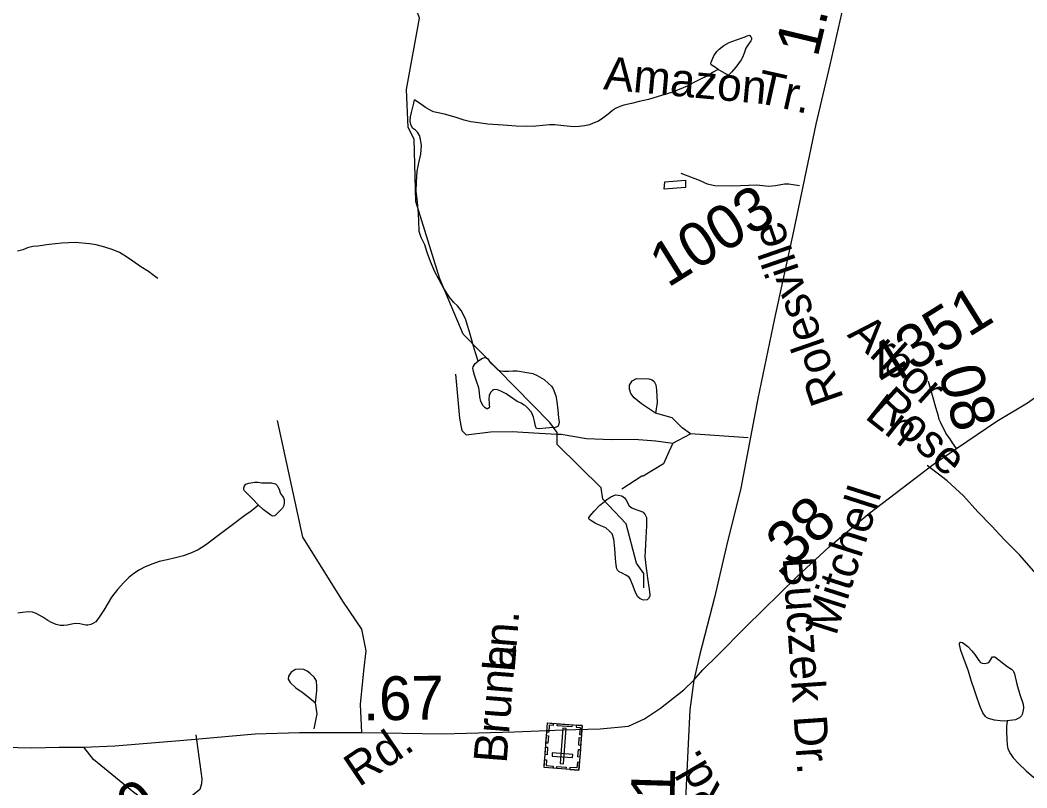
# Model space of a CAD drawing. Extents: x 2001466 to 31450019, y -30647475 to 847247.
# Drawn here: x 2159166 to 2164923, y 774589 to 778978 of the extents above; entities that cross this region are included whole.
import ezdxf

# ---------------------------------------------------------------- set-up
doc = ezdxf.new("R2010")
doc.units = 0
for name, color, linetype in [('Exist Cultural Cemetery CELL', 7, 'Continuous'), ('Exist Hydrographic Creek Single Shore', 7, 'Continuous'), ('Exist Hydrographic Misc Water Feature', 7, 'Continuous'), ('Exist Road Non-System Type 51', 7, 'Continuous'), ('Exist Road Non-System Type 51 Label', 7, 'Continuous'), ('Exist Road Secondary Mileage Hundredths English Label', 7, 'Continuous'), ('Exist Road Secondary Type 51 Attributed', 7, 'Continuous'), ('Exist Road Secondary Type 51 Label', 7, 'Continuous'), ('Exist Road Secondary Type 51 Number Label', 7, 'Continuous')]:
    doc.layers.add(name, color=color, linetype=linetype)

msp = doc.modelspace()

# ---------------------------------------------------------------- linework, layer by layer
at = {"layer": 'Exist Cultural Cemetery CELL'}
for points in [[(2162360.6, 774691), (2162162.1, 774706.1), (2162181.4, 774960), (2162379.9, 774944.9)], [(2162214.4, 774957.5), (2162213.6, 774946), (2162191.6, 774947.7), (2162188.6, 774907.4), (2162177.5, 774908.2), (2162181.4, 774960)], [(2162321.7, 774937.8), (2162237.1, 774944.3), (2162238, 774955.6), (2162322.6, 774949.2)], [(2162346.9, 774947.4), (2162346.1, 774935.9), (2162368, 774934.3), (2162364.9, 774894), (2162376, 774893.1), (2162380, 774944.9)], [(2162187.3, 774887.1), (2162184, 774843.9), (2162172.6, 774844.7), (2162175.9, 774887.9)], [(2162254.2, 774728.5), (2162272.8, 774727.1), (2162288.1, 774929.3), (2162269.5, 774930.7)], [(2162374.7, 774875.2), (2162371.4, 774832), (2162360, 774832.9), (2162363.3, 774876.1)], [(2162182.2, 774821.3), (2162179, 774778.2), (2162167.6, 774779), (2162170.9, 774822.2)], [(2162325.1, 774762), (2162326.5, 774780.6), (2162209.1, 774789.5), (2162207.7, 774770.9)], [(2162369.6, 774808.2), (2162366.3, 774765), (2162354.9, 774765.8), (2162358.2, 774809)], [(2162165.3, 774749.3), (2162176.7, 774748.5), (2162174.2, 774716.4), (2162214.7, 774713.3), (2162213.8, 774702.2), (2162162.1, 774706.1)], [(2162286.8, 774696.7), (2162235.1, 774700.6), (2162236, 774711.9), (2162287.7, 774708)], [(2162363.9, 774734.2), (2162352.6, 774735.1), (2162350.2, 774703), (2162309.7, 774706.1), (2162308.9, 774695), (2162360.6, 774691)]]:
    msp.add_lwpolyline(points, close=True, dxfattribs=at)
at = {"layer": 'Exist Hydrographic Creek Single Shore'}
for points in [[(2162195.3, 776678.1), (2161700.3, 777183.6), (2161565.1, 777498.1), (2161429.2, 777940.4), (2161419.2, 778298.2), (2161385.3, 778364.5), (2161376.3, 778581.3), (2161449.3, 778989.8), (2161347.2, 779280.6), (2161263.3, 779397.2), (2160987.3, 779563.5), (2160886.2, 779710), (2160878.2, 779779), (2160818.1, 779911.5), (2160516.3, 780291.7), (2160201, 780633.1)], [(2162237.3, 776611.6), (2162237.3, 776621.5), (2162195.3, 776678.1)], [(2162733.1, 775732.1), (2162733.1, 775814.1), (2162691.3, 775874), (2162631.2, 776098.3), (2162497.3, 776238.9), (2162488.3, 776304.7), (2162237.3, 776552.5), (2162237.3, 776611.6)]]:
    msp.add_lwpolyline(points, dxfattribs=at)
at = {"layer": 'Exist Hydrographic Misc Water Feature'}
for points in [[(2163157.8, 778696.5), (2163147.7, 778702.5), (2163117.8, 778722), (2163115.8, 778727.9), (2163117.4, 778737.8), (2163133.2, 778774), (2163149.2, 778798.4), (2163163.3, 778812.4), (2163191, 778832.6), (2163220.7, 778850.8), (2163262.6, 778864.8), (2163306.7, 778881.3), (2163332.5, 778891.1), (2163338.6, 778889.4), (2163342.5, 778885.2), (2163346.6, 778881.3), (2163348.5, 778875.3), (2163348.5, 778867.2), (2163344.6, 778859.3), (2163330.9, 778841.1), (2163316.7, 778817.2), (2163309.3, 778795.2), (2163301.3, 778772.9), (2163297.4, 778765), (2163289.6, 778751.2), (2163259.7, 778709), (2163234.1, 778680.9), (2163215.8, 778660.5), (2163208, 778666.6), (2163157.8, 778696.5)], [(2163157.8, 778696.5), (2163149.8, 778692.4), (2163126.2, 778678.1), (2163101.8, 778661.9), (2163064.3, 778643.7), (2163014.5, 778619.6), (2162980.4, 778601.2), (2162934.5, 778580.9), (2162891, 778564.8), (2162832.8, 778546.4), (2162790.7, 778534.1), (2162758.8, 778523.9), (2162706.7, 778512), (2162662.8, 778501.5), (2162619.1, 778491.5), (2162595.3, 778483.4), (2162571.1, 778473.2), (2162553.3, 778460.9), (2162529.5, 778441), (2162497.5, 778416.6), (2162473.5, 778400.4), (2162443.8, 778388.2), (2162421.7, 778380.2), (2162394, 778373.9), (2162362.2, 778369.7), (2162332, 778367.8), (2162276.1, 778373.4), (2162224, 778379.3), (2162194, 778378.9), (2162154.3, 778376.4), (2162114.1, 778372.4), (2162063.8, 778370.2), (2162001.7, 778371.9), (2161927.9, 778377.4), (2161839.9, 778383), (2161788, 778390.4), (2161744, 778396.3), (2161706, 778406.1), (2161653.7, 778423.7), (2161591.8, 778439.6), (2161529.5, 778453.1), (2161513.9, 778461.1), (2161483.5, 778478.6), (2161457.3, 778496.8), (2161421.2, 778522.6)], [(2161785.8, 777028.9), (2161769.6, 777076.8), (2161759.3, 777114.9), (2161744.8, 777160.9), (2161734.7, 777202.6), (2161724.5, 777232.5), (2161714.4, 777264.4), (2161700.3, 777296.2), (2161688.2, 777318.3), (2161666.2, 777344.3), (2161645.7, 777364.1), (2161621.7, 777394.1), (2161589.5, 777443.6), (2161563.1, 777493.4), (2161536.6, 777539.2), (2161512.5, 777597.2), (2161494.2, 777649.1), (2161479.8, 777693), (2161459.8, 777735), (2161447.4, 777768.9), (2161445, 777830.9), (2161444.8, 777870.7), (2161440.7, 777916.8), (2161436.6, 777956.7), (2161430, 777998.7), (2161431.9, 778050.8), (2161435.8, 778114.7), (2161445, 778162.8), (2161457.3, 778210.8), (2161461, 778260.6), (2161456.3, 778296.6), (2161450.5, 778318.6), (2161438.2, 778336.6), (2161426.3, 778348.6), (2161410.3, 778360.3), (2161400.1, 778380.5), (2161395.8, 778400.3), (2161398, 778424.3), (2161403.8, 778450.6), (2161417.5, 778502.4), (2161421.2, 778522.6)], [(2162971.8, 778021.5), (2162849.8, 778010.8), (2162853.3, 778052.9), (2162971.6, 778063.4), (2162971.8, 778021.5)], [(2159953.6, 777500.3), (2159939.5, 777510.2), (2159925.3, 777522.4), (2159899.5, 777540.2), (2159855.2, 777568), (2159810.7, 777599.4), (2159775, 777625.5), (2159734.4, 777649.1), (2159692.8, 777666.7), (2159651, 777680.8), (2159600.5, 777692.5), (2159562.4, 777698.2), (2159480.4, 777705.8), (2159404.3, 777703.1), (2159332.7, 777694.8), (2159266.9, 777686.5), (2159238.8, 777684.3), (2159208.7, 777676.3), (2159180.6, 777663.9), (2159151.1, 777657.8)], [(2162193.6, 776647.6), (2162171.5, 776645.2), (2162131.7, 776641.1), (2162119.6, 776642.9), (2162117.8, 776646.9), (2162113.5, 776656.9), (2162107.5, 776685), (2162101.8, 776708.9), (2162089.5, 776736.8), (2162066.9, 776762.5), (2162055, 776772.4), (2162045, 776778.4), (2162030.8, 776788.6), (2162013, 776796.2), (2162002.9, 776802.1), (2161970.9, 776824), (2161944.5, 776841.8), (2161914.6, 776857.8), (2161896.3, 776863.7), (2161880.5, 776865.7), (2161872.3, 776865.3), (2161866.6, 776861.3), (2161856.5, 776849.5), (2161848.9, 776831.2), (2161846.9, 776809.5), (2161849.1, 776789.3), (2161848.7, 776777.2), (2161849.4, 776767.4), (2161847.5, 776761.2), (2161839.3, 776755.5), (2161835.4, 776755.3), (2161825.4, 776761.3), (2161813.3, 776773.2), (2161801.2, 776797), (2161794.8, 776825.2), (2161792.8, 776848.9), (2161788.5, 776876.8), (2161776.1, 776914.8), (2161764.5, 776949), (2161757.9, 776968.6), (2161754, 776988.7), (2161756.3, 776996.9), (2161767.7, 777015), (2161785.8, 777028.9)], [(2161785.8, 777028.9), (2161789.9, 777032.8), (2161809.8, 777045.2), (2161823.5, 777049.2), (2161833.4, 777047.3), (2161839.7, 777041.1), (2161853.9, 777021.5), (2161877.9, 776997.6), (2161897.7, 776979.5), (2161911.7, 776973.8), (2161930.1, 776971.8), (2161960.3, 776971.7), (2161984.1, 776972.2), (2162007.9, 776972.2), (2162020, 776970.4), (2162064, 776964.5), (2162097.9, 776958.6), (2162122.3, 776946.8), (2162162.1, 776923.3), (2162188.3, 776901.5), (2162204.7, 776885.2), (2162214.3, 776869.6), (2162228.5, 776829.7), (2162234.6, 776797.5), (2162241.2, 776747.5), (2162245.5, 776703.8), (2162247.8, 776679.6), (2162247.4, 776669.9), (2162243.5, 776659.5), (2162240, 776655.6), (2162225.8, 776649.6), (2162193.6, 776647.6)], [(2160529, 776206.1), (2160496.4, 776239.8), (2160448.2, 776287.6), (2160444.3, 776295.5), (2160444.5, 776303.6), (2160448.2, 776315.6), (2160456.2, 776325.8), (2160474.3, 776331.5), (2160508.1, 776335.7), (2160528, 776336), (2160546, 776332.1), (2160604.1, 776332.6), (2160616, 776328.4), (2160626, 776326.5), (2160636.3, 776316.8), (2160639.7, 776310.6), (2160646.5, 776296.6), (2160652.1, 776276.6), (2160656.4, 776268.7), (2160666.6, 776257), (2160672.6, 776246.8), (2160676.5, 776234.8), (2160676.5, 776217), (2160674.6, 776203.1), (2160666.8, 776188.8), (2160658.6, 776180.7), (2160643.2, 776164.8), (2160622.9, 776144.8), (2160611, 776142.5), (2160598.7, 776148.4), (2160554.9, 776180.2), (2160529, 776206.1)], [(2162513.9, 776231.2), (2162521.7, 776237.3), (2162543.5, 776253.5), (2162569.9, 776263.7), (2162585.7, 776261.7), (2162606, 776257.8), (2162621.6, 776247.8), (2162633.9, 776232.1), (2162641.9, 776213.8), (2162649.7, 776202.2), (2162664.2, 776190.2), (2162676.5, 776184.3), (2162698.3, 776176.6), (2162716.3, 776170.6), (2162728, 776164.7), (2162740.7, 776150.6), (2162748.5, 776134.8), (2162748.7, 776086.6), (2162745, 776018.6), (2162739.5, 775944.8), (2162737.6, 775910.6), (2162741.7, 775876.7), (2162746.2, 775844.8), (2162749.9, 775819), (2162752.4, 775802.8), (2162754.2, 775788.8), (2162762.9, 775725), (2162766.8, 775692.8), (2162766.8, 775685.1), (2162759, 775670.8), (2162751, 775664.7), (2162731.3, 775662.8), (2162711, 775668.8), (2162698.9, 775680.7), (2162684.9, 775706.3), (2162671, 775742.5), (2162654.6, 775784.4), (2162648.4, 775794.2), (2162630.2, 775805.9), (2162608.5, 775816.1), (2162592.3, 775823.8), (2162582, 775833.9), (2162578.3, 775841.7), (2162574, 775861.9), (2162569.7, 775899.9), (2162567.4, 775957.8), (2162561.3, 776009.9), (2162551.2, 776041.4), (2162536.9, 776057.3), (2162514.7, 776075.3), (2162486.4, 776087.3), (2162454.7, 776103), (2162434.8, 776113), (2162424.5, 776121), (2162418.8, 776126.7), (2162418.6, 776132.8), (2162424.5, 776142.9), (2162448.3, 776170.9), (2162481.9, 776205.2), (2162505.9, 776223.5), (2162513.9, 776231.2)], [(2160529, 776206.1), (2160487.2, 776171.8), (2160450.9, 776145.6), (2160373.2, 776087.2), (2160303.7, 776034.8), (2160256.1, 775998.6), (2160226, 775976.4), (2160184.1, 775950.3), (2160146.4, 775932.1), (2160100.3, 775915.9), (2160054.5, 775903.3), (2160006.8, 775893.1), (2159961, 775883), (2159924.9, 775870.6), (2159881.1, 775852.5), (2159849.1, 775836.2), (2159815.2, 775814.2), (2159787.3, 775792.1), (2159759.7, 775763.8), (2159721.9, 775723.6), (2159687.7, 775679.3), (2159668.4, 775647.3), (2159644.4, 775605.1), (2159618.6, 775565.2), (2159598.5, 775539.1), (2159585, 775531), (2159569.2, 775522.8), (2159553.2, 775518.8), (2159541.1, 775518.5), (2159507.2, 775526.5), (2159481.2, 775528.4), (2159460.9, 775524.2), (2159435.1, 775519.9), (2159414.8, 775517.7), (2159395.3, 775517.8), (2159371.1, 775523.5), (2159345.3, 775533.6), (2159324.5, 775545.2), (2159294.8, 775565.1), (2159256.9, 775585.1), (2159236.6, 775593), (2159212.6, 775594.6), (2159178.5, 775592.4), (2159152.9, 775588.6)], [(2164810.5, 774972.8), (2164794.3, 774970.7), (2164770.5, 774972.7), (2164738.3, 774976.4), (2164704.7, 774986.3), (2164692, 774991.9), (2164686.2, 774998), (2164672.1, 775018), (2164657.9, 775047.8), (2164639.7, 775101.6), (2164621.2, 775153.5), (2164607.3, 775197.4), (2164588.8, 775255.3), (2164558.7, 775339), (2164546.4, 775375), (2164538, 775409.1), (2164538.2, 775415.2), (2164540, 775421), (2164545.8, 775422.9), (2164556, 775421), (2164586.2, 775397.3), (2164608.1, 775373.3), (2164626.2, 775351.5), (2164648.5, 775317.7), (2164658.4, 775305.7), (2164668.4, 775301.7), (2164682.6, 775300), (2164700.2, 775304.2), (2164710.4, 775312), (2164716.4, 775322.1), (2164722.3, 775332.1), (2164726.2, 775338), (2164732.4, 775338.3), (2164740.4, 775338.3), (2164748.4, 775332.3), (2164808.9, 775284.5), (2164834.7, 775266.9), (2164845, 775258.8), (2164846.8, 775254.9), (2164853, 775241), (2164865.1, 775181.2), (2164883.5, 775123.2), (2164901.8, 775067.2), (2164904, 775047.5), (2164902, 775033.2), (2164896.4, 775009.3), (2164892.1, 775001), (2164880.2, 774989), (2164858.1, 774978.9), (2164810.5, 774972.8)], [(2164810.5, 774972.8), (2164806.4, 774940.5), (2164806.8, 774912.9), (2164809.1, 774864.7), (2164811.1, 774834.7), (2164815.2, 774813), (2164829.4, 774782.9), (2164845.4, 774761), (2164878, 774727.3), (2164919.8, 774685.6), (2164960.2, 774649.5), (2164994.2, 774622.1), (2165020.7, 774601.8), (2165044.5, 774582)]]:
    msp.add_lwpolyline(points, dxfattribs=at)
at = {"layer": 'Exist Road Non-System Type 51'}
for p in [(2162898.5, 776558.7), (2163329, 776590.6)]:
    msp.add_line(p, (2162999.8, 776613.3), dxfattribs=at)
for points in [[(2162944.1, 778103.3), (2163049.1, 778062.8), (2163094.6, 778041.7), (2163138.4, 778032.6), (2163238.3, 778030.2), (2163378.4, 778036.8), (2163448.2, 778029.1), (2163486.3, 778032.1), (2163536.5, 778042.9), (2163562.5, 778042.3), (2163622.2, 778032.8)], [(2161656.4, 776954.9), (2161678.3, 776702.4), (2161685.2, 776660.3), (2161692.6, 776632.1), (2161715.9, 776607.5), (2161856.3, 776624.1), (2161980.4, 776627.1), (2162134.1, 776617.3), (2162237.3, 776611.6)], [(2162798.7, 776731.1), (2162720, 776785), (2162676.9, 776818.1), (2162657.5, 776842.6), (2162650.1, 776868.7), (2162650.6, 776890.7), (2162665.3, 776916.4), (2162691.6, 776929.7), (2162761.5, 776928), (2162779.4, 776921.6), (2162791.1, 776911.3), (2162800.7, 776893.1), (2162805.9, 776862.9), (2162808.2, 776792.9), (2162798.7, 776731.1)], [(2162999.8, 776613.3), (2162951.5, 776647.4), (2162894.7, 776704.2), (2162798.7, 776731.1)], [(2161120.7, 774906.1), (2161112.1, 775065.5), (2161130.6, 775258.6), (2161144.8, 775372.2), (2161119.2, 775495.8), (2161015.6, 775650.6), (2160782.9, 776022.6), (2160638.1, 776690)], [(2162237.3, 776611.6), (2162259.9, 776610.3), (2162405.3, 776586.8), (2162547.1, 776581.3), (2162677.1, 776582.1), (2162800.9, 776573.1), (2162898.5, 776558.7)], [(2162898.5, 776558.7), (2162875.3, 776509.3), (2162845.7, 776442.1), (2162728, 776370.9), (2162722, 776371.1), (2162606.2, 776295.9)], [(2166520.7, 774794.9), (2166259.7, 774833.3), (2165987.6, 774909.9), (2165934.1, 774927.2), (2165884.6, 774950.4), (2165793.6, 774988.6), (2165671.3, 775057.5), (2165557.5, 775146.3), (2165447.7, 775234.9), (2165334.2, 775339.7), (2165246.5, 775429.8), (2165165.6, 775582.4), (2165086.1, 775661.9), (2165003.8, 775781.2), (2164881.7, 775920.4), (2164793.8, 776008.4), (2164722.8, 776085.1), (2164643.3, 776167.5), (2164561, 776258.3), (2164467.3, 776343.5), (2164353.8, 776431.6)], [(2160854.8, 775074.8), (2160862.5, 775144.6), (2160863, 775166.6), (2160859.9, 775200.7), (2160846.4, 775221), (2160824.9, 775243.5), (2160807.2, 775255.9), (2160787.5, 775266.4), (2160771.5, 775266.8), (2160741.5, 775265.5), (2160715.1, 775250.2), (2160700.6, 775228.5), (2160698.1, 775210.6), (2160709.7, 775192.3), (2160742.9, 775161.5), (2160778.3, 775136.7), (2160811.7, 775111.8), (2160854.8, 775074.8)], [(2160848.1, 774926.4), (2160865.3, 775012.6), (2160854.8, 775074.8)], [(2160169.7, 774892.3), (2160204.4, 774640.7), (2160203.7, 774612.7), (2160192.9, 774579), (2160129.6, 774526.6), (2160110.9, 774499), (2160102, 774461.3), (2160092.8, 774411.5), (2160069.6, 774362.1)]]:
    msp.add_lwpolyline(points, dxfattribs=at)
at = {"layer": 'Exist Road Secondary Type 51 Attributed'}
for points in [[(2164284.4, 780973.2), (2164245.2, 780799.4), (2164181.4, 780543.9), (2164093.5, 780095.7), (2163977.3, 779542.8), (2163910.3, 779226.6), (2163796.3, 778721.9), (2163716.8, 778382.6), (2163588.1, 777771.1), (2163479.2, 777272.7), (2163384, 776814), (2163287.7, 776303), (2163205.1, 775972.1), (2163136, 775676.8), (2163052.3, 775354.3), (2163018.8, 775205.6)], [(2164521.7, 776529.3), (2164751.6, 776686.3), (2164927.4, 776791), (2165040.3, 776872), (2165199.5, 776985.7), (2165401.4, 777147), (2165648.4, 777364.8), (2165815.8, 777515.6), (2166043.9, 777746), (2166243.8, 777955.4), (2166348.4, 778053.8), (2166635.1, 778292.6), (2167151, 778700.9), (2167490, 778952.2), (2167628.2, 779046.5), (2167909.6, 779295.7), (2168223.5, 779588.9), (2168351.2, 779699.9), (2168583.5, 779880), (2168875.4, 780089.4), (2169028.2, 780198.3), (2169124.5, 780265.3)], [(2164521.7, 776529.3), (2164498.4, 776561.6), (2164482, 776586.7), (2164469.5, 776604), (2164460.3, 776617.5), (2164451.2, 776633.9), (2164437.2, 776661.9), (2164429, 776679.2), (2164422.2, 776695.2), (2164416.9, 776713.5), (2164402.4, 776764.3), (2164391.3, 776805.3), (2164361.1, 776911.7)], [(2163018.8, 775205.6), (2163070.1, 775263.2), (2163154.8, 775344.9), (2163316, 775510.3), (2163606.9, 775796.2), (2163792.1, 775967.9), (2164024.4, 776160.6), (2164386.4, 776437), (2164521.7, 776529.3)], [(2155516.8, 775501), (2155633.8, 775506.4), (2155791.8, 775508.5), (2155941.5, 775502.2), (2156125.1, 775481.3), (2156305.1, 775461.4), (2156523.8, 775433.1), (2156834, 775393.3), (2157061.1, 775346.2), (2157298.6, 775295.9), (2157675.8, 775201.7), (2158013.8, 775103.3), (2158379.5, 775002.7), (2158539.6, 774957.7), (2158791.8, 774868.7), (2158911.1, 774834.2), (2158988.5, 774823.7), (2159231.8, 774818.4), (2159389.8, 774821.6), (2159530, 774822.6)], [(2159530, 774822.6), (2159707, 774828.7), (2160102.5, 774862.2), (2160510.6, 774897.8), (2160762.8, 774906.1), (2161120.7, 774906.1), (2161581.1, 774897.8), (2161992.3, 774910.3), (2162270.7, 774920.8), (2162482, 774927.1), (2162645.3, 774941.7), (2162737.3, 774983.6), (2162827.9, 775044.4), (2162961.8, 775150.1), (2163018.8, 775205.6)], [(2163018.8, 775205.6), (2162994.8, 775036), (2162986.9, 774840.2), (2162967.5, 774443.3), (2162955.5, 774115.6), (2162947.1, 773814), (2162939.3, 773569)], [(2163038.1, 771744.1), (2162899.4, 771805.9), (2162698.5, 771919), (2162427.5, 772102.2), (2162212.5, 772261.4), (2162128.7, 772339.9), (2161777.7, 772653), (2161392.1, 773037.3), (2161180.7, 773265.6), (2161035.8, 773401.7), (2160910.2, 773579.7), (2160735, 773826.8), (2160633.5, 773943), (2160542.4, 774025.8), (2160255.2, 774245.7), (2159815.7, 774561.9), (2159585.5, 774750.4), (2159530, 774822.6)]]:
    msp.add_lwpolyline(points, dxfattribs=at)

# ---------------------------------------------------------------- texts
at = {"layer": 'Exist Road Non-System Type 51 Label'}
for s, rotation, p in [('Amazon', 354.74059, (2162498.3, 778582.8)), ('Tr.', 347.32762, (2163365.7, 778509.8)), ('Buczek', 273.95101, (2163526.4, 775904.6)), ('Ln.', 85.48734, (2161993, 775245.7)), ('Bruna', 85.48734, (2161947.8, 774726.2)), ('Dr.', 273.95101, (2163588.9, 774998.9))]:
    msp.add_text(s, height=190, rotation=rotation, dxfattribs=at).set_placement(p)
at = {"layer": 'Exist Road Secondary Mileage Hundredths English Label'}
for s, rotation, p in [('1.14', 76.54778, (2163726, 778759.6)), ('.08', 285.89512, (2164389, 777057.9)), ('.38', 42.83681, (2163508.6, 775780.9)), ('.67', 0.8956, (2161126.8, 774973.7)), ('.31', 88.37723, (2162899.6, 774237))]:
    msp.add_text(s, height=250, rotation=rotation, dxfattribs=at).set_placement(p)
at = {"layer": 'Exist Road Secondary Type 51 Label'}
for s, rotation, p in [('Rolesville', 109.10736, (2163877, 776815.2)), ('Arbor', 317.78653, (2163890.7, 777174.1)), ('Rose', 317.70246, (2164033.4, 776758.6)), ('Ln', 321.77569, (2163990.4, 776705.3)), ('Mitchell', 72.29702, (2163831.7, 775453.3)), ('Rd.', 34.10044, (2161103.1, 774590.9)), ('Rd.', 120.29526, (2163238.6, 774483.3))]:
    msp.add_text(s, height=190, rotation=rotation, dxfattribs=at).set_placement(p)
at = {"layer": 'Exist Road Secondary Type 51 Number Label'}
for s, p in [('1003', (2162869.9, 777445.5)), ('4351', (2164115.5, 776866.7)), ('2230', (2159347.9, 774050.3))]:
    msp.add_text(s, height=250, rotation=31.91803, dxfattribs=at).set_placement(p)

doc.saveas('drawing.dxf')
